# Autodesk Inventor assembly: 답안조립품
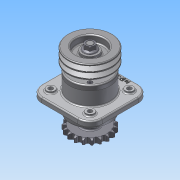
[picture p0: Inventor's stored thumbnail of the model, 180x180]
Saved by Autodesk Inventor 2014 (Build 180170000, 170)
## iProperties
Created: 2015-09
Part Number: 답안조립품
Document SubType Name: Assembly
Designer: study
Author: study
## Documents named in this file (12)
- C:\Users\study\Desktop\450909V1001\답안조립품.iam
- C:\Users\study\Desktop\450909V1001\1-본체.ipt
- C:\Users\study\Desktop\450909V1001\3-축.ipt
- C:\Users\study\Desktop\450909V1001\6-베어링 6206.ipt
- C:\Users\study\Desktop\450909V1001\7-부시.ipt
- C:\Users\study\Desktop\450909V1001\2-커버.ipt
- C:\Users\study\Desktop\450909V1001\8-오일실 30x42.ipt
- C:\Users\study\Desktop\450909V1001\11-키 6x6.ipt
- C:\Users\study\Desktop\450909V1001\4-V벨트풀리.ipt
- C:\Users\study\Desktop\450909V1001\5-체인 스프로킷.ipt
- C:\Users\study\Desktop\450909V1001\9-M16-너트.ipt
- C:\Users\study\Desktop\450909V1001\10-M6.ipt
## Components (23 placed, 11 different names)
1. 1-본체:1
2. 3-축:1 — 각도:1, 각도:2
3. 6-베어링 6206:1
4. 6-베어링 6206:2
5. 7-부시:2
6. 2-커버:1
7. 8-8-오일실 30x42:1
8. 2-커버:2
9. 8-8-오일실 30x42:2
10. 11-키 6x6:1 — 각도:1, 각도:4
11. 11-키 6x6:2 — 각도:2, 각도:3
12. 4-V벨트풀리:1 — 각도:3, 각도:5
13. 5-체인 스프로킷:1 — 각도:4, 각도:6
14. 9-M16 너트:1 — 각도:5
15. 9-M16 너트:2 — 각도:6
16. 10-M6:1
17. 10-M6:3
18. 10-M6:4
19. 10-M6:5
20. 10-M6:2
21. 10-M6:6
22. 10-M6:7
23. 10-M6:8
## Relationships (6: Angle 6)
- 각도:1 [Angle]: 3-축:1 ↔ 11-키 6x6:1
- 각도:2 [Angle]: 3-축:1 ↔ 11-키 6x6:2
- 각도:3 [Angle]: 11-키 6x6:2 ↔ 4-V벨트풀리:1
- 각도:4 [Angle]: 11-키 6x6:1 ↔ 5-체인 스프로킷:1
- 각도:5 [Angle]: 4-V벨트풀리:1 ↔ 9-M16 너트:1
- 각도:6 [Angle]: 5-체인 스프로킷:1 ↔ 9-M16 너트:2
